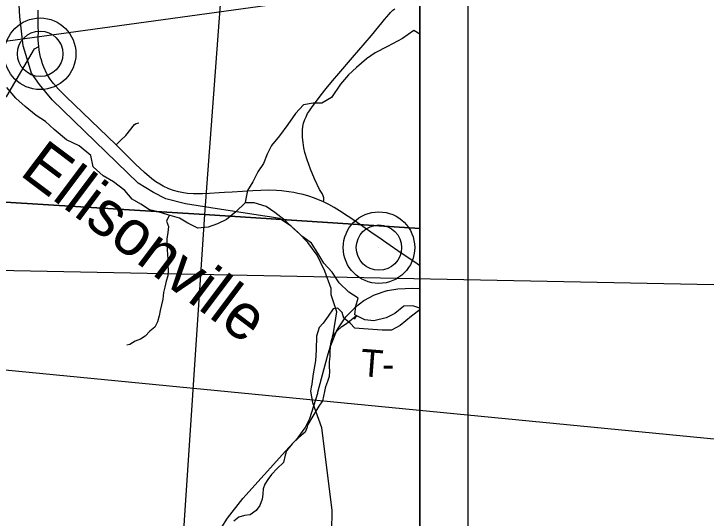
# Model space of a CAD drawing. Extents: x 0 to 44, y -23.8 to 22.
# Drawn here: x 8.055 to 9.496, y 16.706 to 17.755 of the extents above; entities that cross this region are included whole.
import ezdxf

# ---------------------------------------------------------------- set-up
doc = ezdxf.new("R2010")
doc.units = 0
for name, color, linetype in [('Default', 7, 'Continuous'), ('GM_X_County_Road', 7, 'Continuous'), ('GM_X_Minor_River', 7, 'Continuous'), ('GM_X_Minor_River_Text', 7, 'Continuous'), ('GM_X_Rail_Line', 7, 'Continuous'), ('GM_X_Section', 7, 'Continuous'), ('GM_X_State_Route', 7, 'Continuous'), ('GM_X_Township_Road', 7, 'Continuous'), ('GM_X_Township_Road_Text', 7, 'Continuous'), ('GM_X_Unincorporated', 7, 'Continuous'), ('GM_X_Unincorporated_Location', 7, 'Continuous'), ('SH_Cut_Line', 7, 'Continuous'), ('SH_Data', 7, 'Continuous')]:
    doc.layers.add(name, color=color, linetype=linetype)

msp = doc.modelspace()

# ---------------------------------------------------------------- linework, layer by layer
at = {"layer": 'Default'}
msp.add_lwpolyline([(7.2787, 14.3616), (7.5613, 14.343), (8.045, 14.3111), (8.4778, 14.2825), (8.9, 14.2547), (8.9, 20.3521), (8.6785, 20.3684), (7.6577, 20.4476), (7.4495, 20.4611), (7.016, 20.4891)], dxfattribs=at)
for points in [[(8.9, 17.3085), (8.9, 18.3242), (8.5278, 18.3516), (8.4522, 17.3376)], [(8.9, 16.2979), (8.9, 17.3085), (8.4522, 17.3376), (8.3848, 16.3266)]]:
    msp.add_lwpolyline(points, close=True, dxfattribs=at)
at = {"layer": 'GM_X_County_Road'}
msp.add_lwpolyline([(7.6845, 17.4488), (7.726, 17.4555), (7.7575, 17.4574), (7.7866, 17.4551), (7.8764, 17.4832), (7.95, 17.5201), (8.0136, 17.5554), (8.0409, 17.5834), (8.0981, 17.6821), (8.1073, 17.6872)], dxfattribs=at)
at = {"layer": 'GM_X_Minor_River'}
for points in [[(8.9, 17.7125), (8.8875, 17.7202), (8.8642, 17.7033), (8.833, 17.6867), (8.8071, 17.6736), (8.7892, 17.6615), (8.7686, 17.643), (8.7515, 17.6283), (8.7354, 17.6086), (8.7163, 17.581), (8.6961, 17.569), (8.6783, 17.5691), (8.6581, 17.5654), (8.6413, 17.548), (8.6252, 17.5249), (8.6084, 17.5015), (8.5916, 17.481), (8.5827, 17.4629), (8.5746, 17.4439), (8.5632, 17.4261), (8.5524, 17.4057), (8.5417, 17.3875), (8.5373, 17.367), (8.5366, 17.3621)], [(8.9, 17.1429), (8.8855, 17.148), (8.8669, 17.147), (8.8483, 17.1319), (8.8304, 17.1225), (8.8042, 17.1169), (8.786, 17.1186), (8.7648, 17.1293), (8.7672, 17.1468), (8.7719, 17.1638), (8.7522, 17.1761), (8.7323, 17.1955), (8.7176, 17.2176), (8.7007, 17.2363), (8.6879, 17.2573), (8.6748, 17.2778), (8.6567, 17.2909), (8.6382, 17.308), (8.6201, 17.3252), (8.5982, 17.3417), (8.5805, 17.3543), (8.5555, 17.3616), (8.5366, 17.3621), (8.5175, 17.3432), (8.498, 17.3274), (8.4794, 17.318), (8.4596, 17.3116), (8.438, 17.3095), (8.4176, 17.3194), (8.4002, 17.3298), (8.3756, 17.3367), (8.3555, 17.3429), (8.3377, 17.3472), (8.3196, 17.359), (8.3019, 17.3698), (8.2864, 17.3873), (8.263, 17.4053), (8.2411, 17.4183), (8.2204, 17.4366), (8.2153, 17.4602), (8.1911, 17.4804), (8.1647, 17.4927), (8.1394, 17.5145), (8.1213, 17.5309), (8.1017, 17.5432), (8.079, 17.5619), (8.0598, 17.5798), (8.0406, 17.6016)], [(8.3786, 17.3359), (8.3728, 17.3237), (8.3769, 17.313), (8.376, 17.3001), (8.3736, 17.2872), (8.3736, 17.2759), (8.3742, 17.2641), (8.3753, 17.2542), (8.376, 17.2447), (8.3759, 17.2322), (8.3766, 17.222), (8.3758, 17.2102), (8.3723, 17.1989), (8.3699, 17.1867), (8.3668, 17.1754), (8.3656, 17.1617), (8.3625, 17.15), (8.3597, 17.1382), (8.3578, 17.1269), (8.3543, 17.1144), (8.3485, 17.1034), (8.3386, 17.0951), (8.3287, 17.0846), (8.3188, 17.0782), (8.3078, 17.0741), (8.2968, 17.0673), (8.2903, 17.0659)], [(8.6658, 16.8974), (8.6909, 16.9391), (8.6982, 16.9504), (8.7005, 16.9599), (8.7028, 16.9697), (8.7048, 16.98), (8.7087, 16.9913), (8.7125, 17.0015), (8.713, 17.011), (8.7123, 17.0213), (8.7124, 17.0311), (8.7139, 17.0421), (8.7136, 17.052), (8.7141, 17.0622), (8.7157, 17.0732), (8.7188, 17.0846), (8.7283, 17.0955), (8.7379, 17.1045), (8.7474, 17.1109), (8.7682, 17.1276), (8.7637, 17.1199)], [(8.6658, 16.8974), (8.6656, 16.8955), (8.6615, 16.8853), (8.6482, 16.8743), (8.6342, 16.861), (8.6225, 16.8466), (8.6202, 16.8371), (8.6168, 16.8223), (8.6032, 16.8098), (8.5915, 16.7969), (8.5836, 16.787), (8.5775, 16.7771), (8.5745, 16.7673), (8.5737, 16.7559), (8.5722, 16.746), (8.5673, 16.7328), (8.5597, 16.7225), (8.5469, 16.7134), (8.5355, 16.7115), (8.5238, 16.7085), (8.5129, 16.6997)]]:
    msp.add_lwpolyline(points, dxfattribs=at)
at = {"layer": 'GM_X_Rail_Line'}
for points in [[(8.7139, 17.0621), (8.7206, 17.0917), (8.7277, 17.135), (8.7158, 17.1704), (8.7154, 17.1837), (8.7025, 17.2199), (8.6863, 17.2529), (8.6673, 17.2792), (8.6472, 17.3002), (8.6329, 17.3128), (8.608, 17.3297), (8.5875, 17.3327), (8.5731, 17.3348), (8.4654, 17.3518), (8.4123, 17.3598), (8.3713, 17.3703), (8.3458, 17.3834), (8.3142, 17.4025), (8.1348, 17.5763), (8.1091, 17.6077), (8.0922, 17.6318), (8.0833, 17.6614), (8.0746, 17.6883), (8.0676, 17.7494), (8.0634, 17.8242)], [(8.7139, 17.0621), (8.7284, 17.0983), (8.7292, 17.0999), (8.7461, 17.1249), (8.7654, 17.1442), (8.7654, 17.145), (8.7839, 17.1587), (8.8056, 17.1708), (8.8322, 17.1796), (8.833, 17.1796), (8.8547, 17.1828), (8.8852, 17.1844), (8.9, 17.1838)], [(8.487, 16.6856), (8.5002, 16.7065), (8.5321, 16.7473), (8.6206, 16.8457), (8.6472, 16.8738), (8.6616, 16.8939), (8.6713, 16.9133), (8.6882, 16.9664), (8.6882, 16.968), (8.7083, 17.0428), (8.7139, 17.0621)]]:
    msp.add_lwpolyline(points, dxfattribs=at)
at = {"layer": 'GM_X_Section'}
for points in [[(7.5123, 18.4238), (8.5278, 18.3516), (8.4522, 17.3376), (7.4446, 17.3999)], [(7.4446, 17.3999), (8.4522, 17.3376), (8.3848, 16.3266), (7.376, 16.3855)]]:
    msp.add_lwpolyline(points, close=True, dxfattribs=at)
at = {"layer": 'GM_X_State_Route'}
for points in [[(8.1073, 17.6872), (8.1062, 17.7004), (8.1062, 17.7091), (8.1064, 17.7152), (8.1063, 17.731), (8.1063, 17.7476), (8.1063, 17.7628)], [(8.1116, 17.6623), (8.11, 17.6686), (8.1086, 17.6751), (8.1079, 17.6804), (8.1073, 17.6872)], [(8.9, 17.2311), (8.8917, 17.2369), (8.8614, 17.2575), (8.8316, 17.2781), (8.8131, 17.2912), (8.8033, 17.2975), (8.7814, 17.3129), (8.7648, 17.3242), (8.7512, 17.3337), (8.7332, 17.3452), (8.7222, 17.3521), (8.7109, 17.3582), (8.6998, 17.3637), (8.6807, 17.3715), (8.6694, 17.3756), (8.6575, 17.379), (8.6464, 17.3816), (8.6381, 17.3833), (8.6279, 17.3851), (8.612, 17.3869), (8.6017, 17.3876), (8.5859, 17.3883), (8.553, 17.3866), (8.5099, 17.3843), (8.494, 17.3833), (8.4823, 17.3827), (8.4622, 17.3813), (8.4482, 17.3807), (8.4289, 17.3805), (8.417, 17.3812), (8.4081, 17.3825), (8.3978, 17.3846), (8.3873, 17.3875), (8.3779, 17.3912), (8.3662, 17.3963), (8.3592, 17.4006), (8.3505, 17.4058), (8.3424, 17.4115), (8.3271, 17.4251), (8.3088, 17.4422), (8.2681, 17.4824), (8.1633, 17.583), (8.1482, 17.5983), (8.1379, 17.6098), (8.1352, 17.6132), (8.1313, 17.619), (8.1263, 17.6267), (8.1242, 17.6305), (8.1177, 17.6443), (8.1152, 17.6509), (8.1119, 17.6611), (8.1116, 17.6623)]]:
    msp.add_lwpolyline(points, dxfattribs=at)
at = {"layer": 'GM_X_Township_Road'}
for points in [[(8.8213, 17.7365), (8.8265, 17.7432), (8.8363, 17.7545), (8.8392, 17.7577), (8.844, 17.7623), (8.8479, 17.7651)], [(8.6998, 17.3637), (8.7005, 17.3685), (8.7003, 17.372), (8.6992, 17.3762), (8.6966, 17.3816), (8.6914, 17.39), (8.6807, 17.4118), (8.6724, 17.4316), (8.6654, 17.4511), (8.661, 17.4663), (8.6586, 17.4766), (8.6571, 17.4872), (8.6562, 17.4975), (8.6561, 17.5056), (8.6563, 17.5133), (8.6569, 17.5206), (8.6583, 17.5273), (8.6608, 17.535), (8.6633, 17.541), (8.6667, 17.5475), (8.6706, 17.5532), (8.6749, 17.5598), (8.6779, 17.5645), (8.685, 17.5736), (8.6951, 17.5862), (8.7051, 17.5997), (8.7187, 17.6158), (8.7316, 17.631), (8.7603, 17.6639), (8.7867, 17.6947), (8.7995, 17.7098), (8.8148, 17.7284), (8.8213, 17.7365)], [(8.2681, 17.4824), (8.2776, 17.4913), (8.2885, 17.5019), (8.3063, 17.5246), (8.31, 17.5271), (8.3153, 17.5282)], [(8.9, 17.1394), (8.8827, 17.1261), (8.8594, 17.1068), (8.8411, 17.0971), (8.8217, 17.0971), (8.783, 17.1), (8.7646, 17.101), (8.7549, 17.1116), (8.7423, 17.1223), (8.7385, 17.1339), (8.7297, 17.1426), (8.7201, 17.1416), (8.7094, 17.1261), (8.6988, 17.1116), (8.691, 17.1029), (8.6852, 17.0845), (8.6843, 17.0565), (8.6833, 17.0332), (8.6785, 17.0061), (8.6756, 16.9858), (8.6754, 16.9848)], [(8.6754, 16.9848), (8.6742, 16.9786), (8.6726, 16.9703), (8.6765, 16.9471), (8.6955, 16.895), (8.7171, 16.722), (8.714, 16.5506), (8.7202, 16.4177), (8.7155, 16.254), (8.7196, 16.1411)]]:
    msp.add_lwpolyline(points, dxfattribs=at)
at = {"layer": 'GM_X_Unincorporated'}
for centre, radius in [((8.1101, 17.6719), 0.0744), ((8.1101, 17.6719), 0.0472), ((8.8151, 17.2688), 0.0744), ((8.8151, 17.2688), 0.0472)]:
    msp.add_circle(centre, radius, dxfattribs=at)
at = {"layer": 'GM_X_Unincorporated_Location'}
for p, q in [((8.1101, 17.6719), (8.1101, 17.6719)), ((8.8151, 17.2688), (8.8151, 17.2688))]:
    msp.add_line(p, q, dxfattribs=at)
at = {"layer": 'SH_Cut_Line'}
msp.add_lwpolyline([(2.838, 14.1), (8.9, 14.1), (8.9, 20.9), (6.8158, 20.9)], dxfattribs=at)
at = {"layer": 'SH_Data'}
for p, q in [((9, 21), (9, 14)), ((8.9, 20.9), (8.9, 14.1))]:
    msp.add_line(p, q, dxfattribs=at)
for points in [[(5.3413, 17.3275), (9.7799, 18.2797), (9.7799, 17.9369)], [(5.3505, 17.2755), (9.7548, 17.1872), (9.7548, 16.8468)]]:
    msp.add_lwpolyline(points, close=True, dxfattribs=at)

# ---------------------------------------------------------------- texts
at = {"layer": 'GM_X_Minor_River_Text'}
msp.add_text('Ellisonville', height=0.094688, rotation=323.0648, dxfattribs=at).set_placement((8.0651, 17.4214))
at = {"layer": 'GM_X_Township_Road_Text'}
for s, rotation, p in [('T', 355.6264, (8.7751, 17.0019)), ('-', 359.3496, (8.8215, 16.9985))]:
    msp.add_text(s, height=0.0568, rotation=rotation, dxfattribs=at).set_placement(p)

doc.saveas('drawing.dxf')
